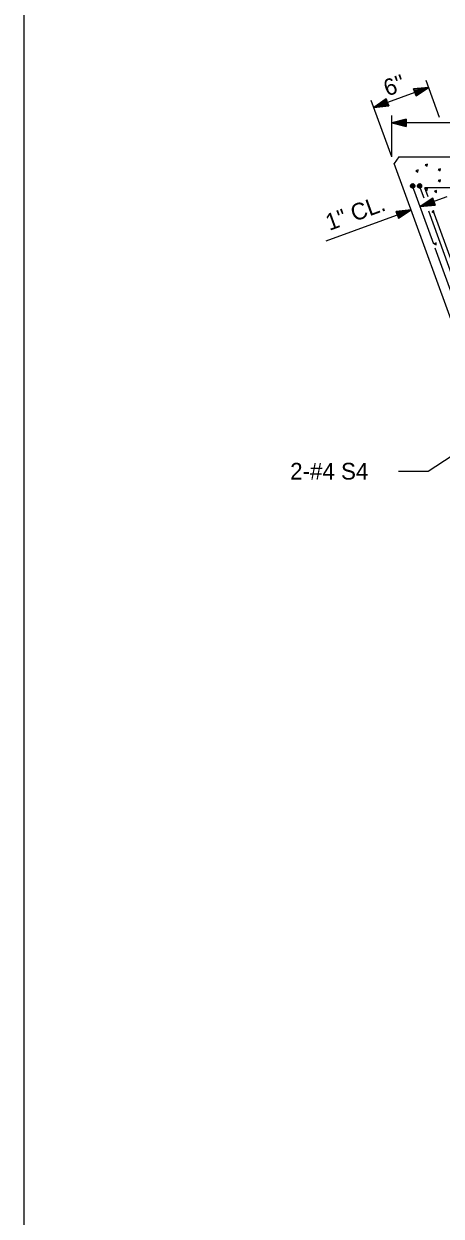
# Model space of a CAD drawing. Extents: x 0 to 177, y -1 to 130.
# Drawn here: x 124.81 to 128.38, y 63.14 to 73.35 of the extents above; entities that cross this region are included whole.
import ezdxf

# ---------------------------------------------------------------- set-up
doc = ezdxf.new("R2010")
doc.units = 0
for name, color, linetype in [('Dimension Lines', 7, 'Continuous'), ('Plan Sheet', 7, 'Continuous'), ('Rebar Lines', 7, 'Continuous'), ('Sup Concrete Girder Lines', 7, 'Continuous'), ('Text', 7, 'Continuous')]:
    doc.layers.add(name, color=color, linetype=linetype)

msp = doc.modelspace()

# ---------------------------------------------------------------- linework, layer by layer
at = {"layer": 'Dimension Lines'}
for p, q in [((128.277, 72.801), (127.807, 72.63)), ((128.371, 72.543), (128.256, 72.86)), ((127.961, 72.208), (127.786, 72.689)), ((127.961, 72.208), (127.961, 72.561)), ((131.753, 72.498), (127.961, 72.498)), ((128.432, 71.864), (128.205, 71.781)), ((127.4, 71.488), (128.127, 71.752))]:
    msp.add_line(p, q, dxfattribs=at)
for points in [[(128.16, 72.758), (128.157, 72.764), (128.277, 72.801), (128.155, 72.77), (128.153, 72.776), (128.277, 72.801), (128.151, 72.782), (128.149, 72.788), (128.277, 72.801), (128.17, 72.729), (128.168, 72.735), (128.277, 72.801), (128.166, 72.741), (128.164, 72.746), (128.277, 72.801), (128.162, 72.752), (128.149, 72.788), (128.17, 72.729), (128.277, 72.801), (128.149, 72.788)], [(127.925, 72.673), (127.927, 72.667), (127.807, 72.63), (127.929, 72.661), (127.931, 72.655), (127.807, 72.63), (127.933, 72.649), (127.935, 72.643), (127.807, 72.63), (127.914, 72.702), (127.916, 72.696), (127.807, 72.63), (127.918, 72.69), (127.92, 72.684), (127.807, 72.63), (127.922, 72.678), (127.935, 72.643), (127.914, 72.702), (127.807, 72.63), (127.935, 72.643)], [(128.086, 72.498), (128.086, 72.505), (127.961, 72.498), (128.086, 72.511), (128.086, 72.517), (127.961, 72.498), (128.086, 72.523), (128.086, 72.53), (127.961, 72.498), (128.086, 72.467), (128.086, 72.473), (127.961, 72.498), (128.086, 72.48), (128.086, 72.486), (127.961, 72.498), (128.086, 72.492), (128.086, 72.53), (128.086, 72.467), (127.961, 72.498), (128.086, 72.53)], [(128.322, 71.824), (128.324, 71.818), (128.205, 71.781), (128.327, 71.812), (128.329, 71.806), (128.205, 71.781), (128.331, 71.8), (128.333, 71.794), (128.205, 71.781), (128.312, 71.853), (128.314, 71.847), (128.205, 71.781), (128.316, 71.841), (128.318, 71.835), (128.205, 71.781), (128.32, 71.83), (128.333, 71.794), (128.312, 71.853), (128.205, 71.781), (128.333, 71.794)], [(128.009, 71.71), (128.007, 71.716), (128.127, 71.752), (128.005, 71.721), (128.003, 71.727), (128.127, 71.752), (128, 71.733), (127.998, 71.739), (128.127, 71.752), (128.02, 71.68), (128.018, 71.686), (128.127, 71.752), (128.015, 71.692), (128.013, 71.698), (128.127, 71.752), (128.011, 71.704), (127.998, 71.739), (128.02, 71.68), (128.127, 71.752), (127.998, 71.739)], [(128.018, 69.515), (128.274, 69.515), (128.964, 69.966)]]:
    msp.add_lwpolyline(points, dxfattribs=at)
at = {"layer": 'Plan Sheet'}
msp.add_line((124.81, 119.135), (124.81, -0.865), dxfattribs=at)
at = {"layer": 'Rebar Lines'}
for p, q in [((128.322, 71.458), (128.14, 71.958)), ((128.238, 71.854), (128.2, 71.958)), ((129.602, 71.942), (128.244, 71.942)), ((128.272, 71.865), (128.244, 71.942)), ((128.574, 70.929), (128.279, 71.741)), ((128.609, 70.942), (128.316, 71.747)), ((128.514, 70.931), (128.334, 71.425))]:
    msp.add_line(p, q, dxfattribs=at)
for points in [[(128.123, 71.955), (128.123, 71.962), (128.126, 71.968), (128.131, 71.973), (128.137, 71.975), (128.144, 71.975), (128.15, 71.972), (128.155, 71.967), (128.158, 71.961), (128.158, 71.954), (128.155, 71.948), (128.15, 71.943), (128.143, 71.941), (128.137, 71.941), (128.13, 71.944), (128.125, 71.948), (128.123, 71.955), (128.14, 71.958), (128.158, 71.961), (128.155, 71.967), (128.14, 71.958), (128.15, 71.972), (128.144, 71.975), (128.14, 71.958), (128.137, 71.975), (128.131, 71.973), (128.14, 71.958), (128.126, 71.968), (128.123, 71.962), (128.14, 71.958), (128.125, 71.948), (128.13, 71.944), (128.14, 71.958), (128.137, 71.941), (128.143, 71.941), (128.14, 71.958), (128.15, 71.943), (128.155, 71.948), (128.14, 71.958), (128.158, 71.954)], [(128.183, 71.955), (128.183, 71.962), (128.186, 71.968), (128.191, 71.973), (128.197, 71.975), (128.204, 71.975), (128.21, 71.972), (128.215, 71.967), (128.217, 71.961), (128.217, 71.954), (128.215, 71.948), (128.21, 71.943), (128.203, 71.941), (128.196, 71.941), (128.19, 71.943), (128.185, 71.948), (128.183, 71.955), (128.2, 71.958), (128.217, 71.961), (128.215, 71.967), (128.2, 71.958), (128.21, 71.972), (128.204, 71.975), (128.2, 71.958), (128.197, 71.975), (128.191, 71.973), (128.2, 71.958), (128.186, 71.968), (128.183, 71.962), (128.2, 71.958), (128.185, 71.948), (128.19, 71.943), (128.2, 71.958), (128.196, 71.941), (128.203, 71.941), (128.2, 71.958), (128.21, 71.943), (128.215, 71.948), (128.2, 71.958), (128.217, 71.954)]]:
    msp.add_lwpolyline(points, dxfattribs=at)
at = {"layer": 'Sup Concrete Girder Lines'}
for p, q in [((128.023, 72.208), (127.982, 72.149)), ((128.023, 72.208), (133.546, 72.208)), ((129.053, 69.208), (127.982, 72.149))]:
    msp.add_line(p, q, dxfattribs=at)
for points in [[(128.186, 72.076), (128.187, 72.094), (128.169, 72.086), (128.186, 72.076)], [(128.265, 72.128), (128.267, 72.145), (128.249, 72.138), (128.265, 72.128)], [(128.377, 72.088), (128.378, 72.105), (128.36, 72.098), (128.377, 72.088)], [(128.377, 71.993), (128.378, 72.01), (128.36, 72.003), (128.377, 71.993)], [(128.265, 71.917), (128.267, 71.935), (128.249, 71.927), (128.265, 71.917)], [(128.345, 71.901), (128.346, 71.919), (128.328, 71.912), (128.345, 71.901)], [(128.321, 71.727), (128.323, 71.744), (128.305, 71.737), (128.321, 71.727)], [(128.341, 71.452), (128.342, 71.47), (128.324, 71.463), (128.341, 71.452)]]:
    msp.add_lwpolyline(points, dxfattribs=at)

# ---------------------------------------------------------------- texts
at = {"layer": 'Text'}
for s, rotation, p in [("6''", 19.9877, (127.923, 72.722)), ('1" CL.', 20.0021, (127.427, 71.572))]:
    msp.add_text(s, height=0.143, rotation=rotation, dxfattribs=at).set_placement(p)
msp.add_text('2-#4 S4', height=0.143, dxfattribs=at).set_placement((127.091, 69.443))

doc.saveas('drawing.dxf')
